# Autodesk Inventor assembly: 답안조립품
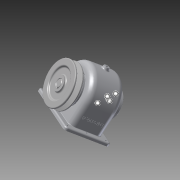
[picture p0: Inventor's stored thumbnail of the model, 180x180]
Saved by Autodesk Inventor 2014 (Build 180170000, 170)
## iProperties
Created: 2015-09
Part Number: 답안조립품
Document SubType Name: Assembly
Designer: SEC
Author: SEC
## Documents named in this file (9)
- C:\Users\SEC\Desktop\450907V1017\답안조립품.iam
- C:\Users\SEC\Desktop\450907V1017\본체.ipt
- C:\Users\SEC\Desktop\450907V1017\앞커버.ipt
- C:\Users\SEC\Desktop\450907V1017\베어링 6203.ipt
- C:\Users\SEC\Desktop\450907V1017\축.ipt
- C:\Users\SEC\Desktop\450907V1017\뒤커버.ipt
- C:\Users\SEC\Desktop\450907V1017\V-벨트풀리.ipt
- C:\Users\SEC\Desktop\450907V1017\스퍼기어.ipt
- C:\Users\SEC\Desktop\450907V1017\볼트 M3 x 8.ipt
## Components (9 placed, 2 different names)
1. V-벨트풀리:1
2. ISO 4762 M3 x 8:1
3. ISO 4762 M3 x 8:2
4. ISO 4762 M3 x 8:3
5. ISO 4762 M3 x 8:4
6. ISO 4762 M3 x 8:5
7. ISO 4762 M3 x 8:6
8. ISO 4762 M3 x 8:7
9. ISO 4762 M3 x 8:8
